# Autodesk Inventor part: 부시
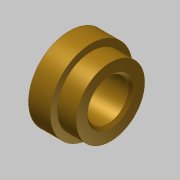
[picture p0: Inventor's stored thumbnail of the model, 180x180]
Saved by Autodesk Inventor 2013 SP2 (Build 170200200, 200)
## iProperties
Created: 2016-05
Part Number: 부시
Document SubType Name: Modeling
Designer: mduedu
Density: 7.86 g/cm^3
Material: 강철, 연강
Author: mduedu
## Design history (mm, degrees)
sketch "스케치1"
  geometry: L1 (0, 0)-(15, 0); L2 (0, 7.5)-(15, 7.5); L3 (15, 7.5)-(15, 12.5); L4 (15, 12.5)-(8, 12.5); L5 (8, 12.5)-(8, 15); L6 (8, 15)-(0, 15); L7 (0, 15)-(0, 7.5)
  constraints: 14 end point, 4 parallel, 2 vertical alignment, 1 horizontal, 1 perpendicular, 1 vertical
  dimensions: "d0" = 15 distance of L1.start L1.end; "d1" = 15 diameter of L2 L1; "d2" = 25 diameter of L4 L1; "d3" = 8 distance of L5.end L6.end; "d4" = 30 diameter of L6 L1
revolve "회전1" sketch "스케치1" stored, may be unused: angle "d5" = 90 deg
chamfer "모따기1" distance "d6" = 1; stored, may be unused: second distance "d7" = 2, angle "d8" = 45 deg
node "솔리드1"
